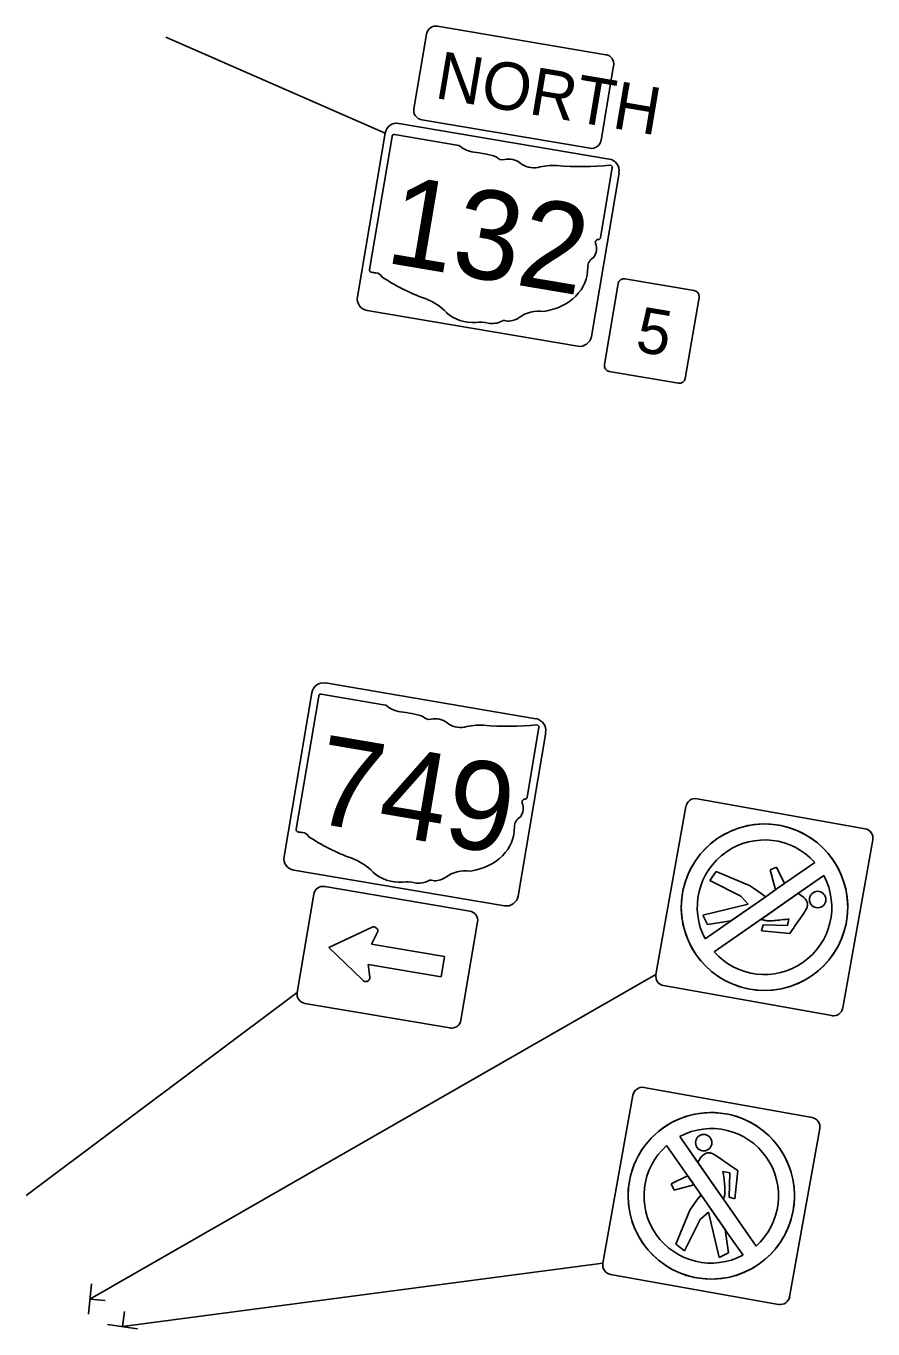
# Model space of a CAD drawing. Extents: x 1482113 to 1482447, y 365324 to 365634.
# Drawn here: x 1482304.2 to 1482393.4, y 365493.8 to 365631 of the extents above; entities that cross this region are included whole.
import ezdxf

# ---------------------------------------------------------------- set-up
doc = ezdxf.new("R2010")
doc.units = 0
doc.layers.add('RS_Raster1', color=7, linetype='Continuous')
doc.layers.add('SC_Scratch1', color=7, linetype='Continuous')

msp = doc.modelspace()

# ---------------------------------------------------------------- linework, layer by layer
at = {"layer": 'RS_Raster1'}
for p, q in [((1482342, 365619.74), (1482318.88, 365629.86)), ((1482345.03, 365622.3), (1482346.36, 365630.18)), ((1482347.52, 365631), (1482365.26, 365628)), ((1482366.08, 365626.85), (1482364.75, 365618.96)), ((1482363.6, 365618.14), (1482345.85, 365621.14)), ((1482342.73, 365619.39), (1482340.36, 365605.36)), ((1482349.77, 365618.45), (1482343, 365619.6)), ((1482364.7, 365608.73), (1482365.94, 365616.07)), ((1482364.69, 365608.74), (1482364.7, 365608.73)), ((1482369.59, 365595.95), (1482369.59, 365595.95)), ((1482335, 365560.44), (1482332.63, 365546.41)), ((1482342.04, 365559.5), (1482335.27, 365560.65)), ((1482356.97, 365549.78), (1482358.21, 365557.12)), ((1482356.96, 365549.79), (1482356.97, 365549.78)), ((1482334.48, 365539.57), (1482332.73, 365529.21)), ((1482350.91, 365537.8), (1482335.63, 365540.39)), ((1482350.91, 365537.8), (1482350.91, 365537.8)), ((1482349.98, 365526.29), (1482351.73, 365536.65)), ((1482336.07, 365533.97), (1482340.62, 365536.09)), ((1482341.17, 365535.52), (1482340.56, 365534.32)), ((1482339.62, 365530.54), (1482336.07, 365533.97)), ((1482340.56, 365534.32), (1482348.26, 365533.02)), ((1482348.26, 365533.02), (1482347.9, 365530.86)), ((1482347.9, 365530.86), (1482340.2, 365532.16)), ((1482340.2, 365532.16), (1482340.38, 365530.83)), ((1482332.73, 365529.21), (1482304.15, 365507.84)), ((1482333.54, 365528.06), (1482348.83, 365525.48))]:
    msp.add_line(p, q, dxfattribs=at)
for points in [[(1482343.44, 365620.77), (1482365.62, 365617.01)], [(1482339.08, 365602.49), (1482342, 365619.74)], [(1482366.65, 365615.57), (1482363.73, 365598.32)], [(1482365.1, 365595.35), (1482366.54, 365603.89)], [(1482367.25, 365604.39), (1482374.57, 365603.16)], [(1482375.08, 365602.44), (1482373.63, 365593.91)], [(1482362.29, 365597.29), (1482340.1, 365601.05)], [(1482372.92, 365593.4), (1482365.6, 365594.64)], [(1482335.71, 365561.82), (1482357.89, 365558.06)], [(1482331.35, 365543.54), (1482334.27, 365560.79)], [(1482358.92, 365556.62), (1482356, 365539.37)], [(1482354.56, 365538.34), (1482332.37, 365542.1)]]:
    msp.add_lwpolyline(points, dxfattribs=at)
for centre, radius, start, end in [((1482347.35, 365630.02), 1, 80.4, 170.4), ((1482365.1, 365627.02), 1, 350.4, 80.4), ((1482346.01, 365622.13), 1, 170.4, 260.4), ((1482343.23, 365619.53), 1.25, 80.4, 170.4), ((1482363.76, 365619.13), 1, 260.4, 350.4), ((1482365.41, 365615.78), 1.25, 350.4, 80.4), ((1482367.15, 365603.78), 0.618, 80.4, 170.4), ((1482340.31, 365602.28), 1.25, 170.4, 260.4), ((1482374.47, 365602.55), 0.618, 350.4, 80.4), ((1482362.5, 365598.53), 1.25, 260.4, 350.4), ((1482365.71, 365595.25), 0.618, 170.4, 260.4), ((1482373.02, 365594.01), 0.618, 260.4, 350.4), ((1482335.5, 365560.58), 1.25, 80.4, 170.4), ((1482357.68, 365556.83), 1.25, 350.4, 80.4), ((1482332.58, 365543.33), 1.25, 170.4, 260.4), ((1482335.46, 365539.4), 1, 80.4, 170.4), ((1482354.77, 365539.58), 1.25, 260.4, 350.4), ((1482350.75, 365536.81), 1, 350.4, 80.4), ((1482340.8, 365535.71), 0.417, 333.1954, 114.9888), ((1482339.96, 365530.78), 0.417, 215.3904, 7.6046), ((1482333.71, 365529.05), 1, 170.4, 260.4), ((1482349, 365526.46), 1, 260.4, 350.4)]:
    msp.add_arc(centre, radius, start, end, dxfattribs=at)
for centre, major_axis, start_param, end_param in [((1482343, 365619.38), (0.268, -0.045), 1.712693, 3.28349), ((1482351.65, 365619.81), (2.6, -0.44), 4.042523, 4.731795), ((1482350.91, 365610.16), (9.32, -1.58), 1.404758, 1.657858), ((1482354.33, 365617.54), (0.749, -0.127), 3.836095, 5.185415), ((1482355.16, 365615.73), (1.56, -0.26), 0.950623, 2.079405), ((1482357.54, 365617.61), (1.87, -0.32), 4.081561, 5.145723), ((1482360.05, 365612.3), (4.93, -0.83), 1.699011, 2.107814), ((1482360.88, 365636.25), (24.51, -4.14), 4.814394, 5.042369), ((1482365.69, 365616.15), (0.257, -0.044), 6.141152, 7.989035), ((1482361.86, 365607.71), (2.39, -0.4), 5.934695, 6.695948), ((1482364.55, 365608.21), (0.398, -0.067), 1.883978, 3.671073), ((1482364.42, 365608.75), (0.275, -0.047), 5.05454, 6.418171), ((1482365.1, 365605.51), (1.74, -0.29), 2.387724, 3.262537), ((1482340.62, 365605.29), (0.27, -0.046), 3.00124, 4.508301), ((1482340.9, 365606.71), (2.06, -0.35), 4.665946, 4.897461), ((1482340.95, 365604.43), (0.743, -0.126), 0.519207, 1.627899), ((1482357.16, 365605.89), (6.13, -1.04), 5.101752, 6.440018), ((1482352.46, 365615.45), (17.7, -2.99), 4.195997, 4.488961), ((1482344.13, 365598.24), (5.54, -0.94), 0.823519, 1.323587), ((1482351.03, 365602.65), (3.51, -0.59), 4.026481, 4.996735), ((1482358.52, 365598.24), (3.36, -0.57), 1.647645, 2.488434), ((1482352.24, 365597.46), (2.89, -0.49), 1.495662, 1.94098), ((1482353.14, 365601.21), (1.87, -0.32), 4.691044, 5.507374), ((1482354.61, 365599.57), (0.527, -0.089), 1.147584, 2.315152), ((1482354.71, 365601.54), (1.98, -0.33), 4.937069, 5.64225), ((1482335.27, 365560.43), (0.268, -0.045), 1.712693, 3.28349), ((1482343.92, 365560.86), (2.6, -0.44), 4.042523, 4.731795), ((1482343.18, 365551.21), (9.32, -1.58), 1.404758, 1.657858), ((1482346.6, 365558.59), (0.749, -0.127), 3.836095, 5.185415), ((1482347.43, 365556.78), (1.56, -0.26), 0.950623, 2.079405), ((1482349.81, 365558.66), (1.87, -0.32), 4.081561, 5.145723), ((1482352.32, 365553.35), (4.93, -0.83), 1.699011, 2.107814), ((1482353.15, 365577.3), (24.51, -4.14), 4.814394, 5.042369), ((1482357.96, 365557.2), (0.257, -0.044), 6.141152, 7.989035), ((1482354.13, 365548.76), (2.39, -0.4), 5.934695, 6.695948), ((1482356.82, 365549.26), (0.398, -0.067), 1.883978, 3.671073), ((1482356.69, 365549.8), (0.275, -0.047), 5.05454, 6.418171), ((1482357.37, 365546.56), (1.74, -0.29), 2.387724, 3.262537), ((1482332.89, 365546.34), (0.27, -0.046), 3.00124, 4.508301), ((1482333.17, 365547.76), (2.06, -0.35), 4.665946, 4.897461), ((1482333.22, 365545.48), (0.743, -0.126), 0.519207, 1.627899), ((1482349.43, 365546.94), (6.13, -1.04), 5.101752, 6.440018), ((1482344.73, 365556.5), (17.7, -2.99), 4.195997, 4.488961), ((1482336.4, 365539.29), (5.54, -0.94), 0.823519, 1.323587), ((1482343.3, 365543.7), (3.51, -0.59), 4.026481, 4.996735), ((1482350.79, 365539.29), (3.36, -0.57), 1.647645, 2.488434), ((1482344.51, 365538.51), (2.89, -0.49), 1.495662, 1.94098), ((1482345.41, 365542.26), (1.87, -0.32), 4.691044, 5.507374), ((1482346.88, 365540.62), (0.527, -0.089), 1.147584, 2.315152), ((1482346.98, 365542.59), (1.98, -0.33), 4.937069, 5.64225)]:
    msp.add_ellipse(centre, major_axis=major_axis, ratio=0.8, start_param=start_param, end_param=end_param, dxfattribs=at)
at = {"layer": 'SC_Scratch1'}
for p, q in [((1482376.88, 365541.95), (1482376.2, 365541.03)), ((1482376.88, 365541.95), (1482376.2, 365541.03)), ((1482380.45, 365540.46), (1482376.88, 365541.95)), ((1482380.45, 365540.46), (1482376.88, 365541.95)), ((1482383.23, 365542.43), (1482382.58, 365542.13)), ((1482383.23, 365542.43), (1482382.58, 365542.13)), ((1482382.58, 365542.13), (1482383.14, 365540.04)), ((1482382.58, 365542.13), (1482383.14, 365540.04)), ((1482384.1, 365540.71), (1482383.23, 365542.43)), ((1482384.09, 365540.71), (1482383.23, 365542.43)), ((1482376.2, 365541.03), (1482379.49, 365539.37)), ((1482376.2, 365541.03), (1482379.49, 365539.37)), ((1482388.24, 365541.54), (1482376.68, 365533.49)), ((1482381.62, 365539.65), (1482380.45, 365540.46)), ((1482381.62, 365539.65), (1482380.45, 365540.46)), ((1482378.42, 365536.75), (1482382, 365539.24)), ((1482379.49, 365539.37), (1482380.25, 365538.51)), ((1482379.49, 365539.37), (1482380.25, 365538.51)), ((1482382.07, 365539.29), (1482381.62, 365539.65)), ((1482382.07, 365539.29), (1482381.62, 365539.65)), ((1482385.4, 365539.56), (1482381.66, 365536.95)), ((1482382, 365539.24), (1482382.07, 365539.29)), ((1482383.14, 365540.04), (1482383.33, 365540.17)), ((1482385.52, 365539.64), (1482385.4, 365539.56)), ((1482380.25, 365538.51), (1482375.47, 365537.37)), ((1482380.25, 365538.51), (1482375.47, 365537.37)), ((1482375.47, 365537.37), (1482375.97, 365536.38)), ((1482375.47, 365537.37), (1482375.97, 365536.38)), ((1482375.97, 365536.38), (1482378.42, 365536.75)), ((1482375.97, 365536.38), (1482378.42, 365536.75)), ((1482381.84, 365536.34), (1482381.67, 365535.73)), ((1482381.84, 365536.34), (1482381.67, 365535.73)), ((1482384.4, 365536.26), (1482381.84, 365536.34)), ((1482384.4, 365536.26), (1482381.84, 365536.34)), ((1482384.55, 365536.97), (1482384.4, 365536.26)), ((1482384.55, 365536.97), (1482384.4, 365536.26)), ((1482381.67, 365535.73), (1482384.66, 365535.42)), ((1482381.67, 365535.73), (1482384.66, 365535.42)), ((1482384.66, 365535.42), (1482384.66, 365535.44)), ((1482384.66, 365535.42), (1482384.66, 365535.44)), ((1482310.88, 365496.92), (1482370.54, 365531.1)), ((1482373.04, 365514.06), (1482381.09, 365502.5)), ((1482374.94, 365511.34), (1482375.02, 365511.22)), ((1482375.02, 365511.22), (1482377.62, 365507.48)), ((1482377.6, 365510.38), (1482378.32, 365510.22)), ((1482377.6, 365510.38), (1482378.32, 365510.22)), ((1482378.85, 365507.49), (1482379.16, 365510.48)), ((1482378.85, 365507.49), (1482379.16, 365510.48)), ((1482379.16, 365510.48), (1482379.14, 365510.48)), ((1482379.16, 365510.48), (1482379.14, 365510.48)), ((1482373.87, 365509.92), (1482372.15, 365509.05)), ((1482373.87, 365509.92), (1482372.15, 365509.05)), ((1482372.15, 365509.05), (1482372.45, 365508.41)), ((1482372.15, 365509.05), (1482372.45, 365508.41)), ((1482372.45, 365508.41), (1482374.54, 365508.96)), ((1482372.45, 365508.41), (1482374.54, 365508.96)), ((1482374.54, 365508.96), (1482374.41, 365509.15)), ((1482378.32, 365510.22), (1482378.24, 365507.66)), ((1482378.32, 365510.22), (1482378.24, 365507.66)), ((1482375.29, 365507.89), (1482374.93, 365507.44)), ((1482375.29, 365507.89), (1482374.93, 365507.44)), ((1482375.33, 365507.82), (1482375.29, 365507.89)), ((1482377.83, 365504.25), (1482375.33, 365507.82)), ((1482378.24, 365507.66), (1482378.85, 365507.49)), ((1482378.24, 365507.66), (1482378.85, 365507.49)), ((1482374.12, 365506.28), (1482372.63, 365502.71)), ((1482374.12, 365506.28), (1482372.63, 365502.71)), ((1482374.93, 365507.44), (1482374.12, 365506.28)), ((1482374.93, 365507.44), (1482374.12, 365506.28)), ((1482373.55, 365502.02), (1482375.21, 365505.31)), ((1482373.55, 365502.02), (1482375.21, 365505.31)), ((1482375.21, 365505.31), (1482376.07, 365506.08)), ((1482375.21, 365505.31), (1482376.07, 365506.08)), ((1482376.07, 365506.08), (1482377.21, 365501.29)), ((1482376.07, 365506.08), (1482377.21, 365501.29)), ((1482378.2, 365501.79), (1482377.83, 365504.25)), ((1482378.2, 365501.79), (1482377.83, 365504.25)), ((1482372.63, 365502.71), (1482373.55, 365502.02)), ((1482372.63, 365502.71), (1482373.55, 365502.02)), ((1482314.31, 365494.02), (1482364.95, 365500.69)), ((1482377.21, 365501.29), (1482378.2, 365501.79)), ((1482377.21, 365501.29), (1482378.2, 365501.79)), ((1482310.73, 365495.33), (1482311.04, 365498.52)), ((1482310.88, 365496.92), (1482312.48, 365496.77)), ((1482314.31, 365494.02), (1482314.54, 365495.6)), ((1482315.89, 365493.78), (1482312.72, 365494.25))]:
    msp.add_line(p, q, dxfattribs=at)
for points in [[(1482373.7, 365548.82), (1482370.54, 365531.1)], [(1482392.58, 365546.47), (1482374.87, 365549.63)], [(1482390.23, 365527.59), (1482393.39, 365545.31)], [(1482387.27, 365542.92), (1482384.13, 365540.73), (1482383.33, 365540.16), (1482383.33, 365540.17)], [(1482383.33, 365540.17), (1482384.09, 365540.71), (1482384.09, 365540.71)], [(1482385.4, 365539.56), (1482388.24, 365541.54)], [(1482383.33, 365540.17), (1482382, 365539.24), (1482377.7, 365536.24), (1482375.72, 365534.86)], [(1482376.68, 365533.49), (1482381.27, 365536.68), (1482381.27, 365536.68), (1482381.27, 365536.68), (1482385.4, 365539.56), (1482385.39, 365539.56)], [(1482385.4, 365539.56), (1482385.4, 365539.56)], [(1482371.35, 365529.94), (1482389.07, 365526.78)], [(1482386.99, 365516.05), (1482369.27, 365519.22)], [(1482368.11, 365518.41), (1482364.95, 365500.69)], [(1482384.63, 365497.17), (1482387.8, 365514.89)], [(1482371.66, 365513.1), (1482373.85, 365509.95), (1482374.41, 365509.16), (1482374.41, 365509.15)], [(1482375.02, 365511.22), (1482373.04, 365514.06)], [(1482381.09, 365502.51), (1482377.9, 365507.09), (1482377.9, 365507.09), (1482377.9, 365507.09), (1482375.02, 365511.22), (1482375.02, 365511.22)], [(1482375.02, 365511.22), (1482375.02, 365511.22)], [(1482374.41, 365509.15), (1482373.87, 365509.92), (1482373.87, 365509.92)], [(1482374.41, 365509.15), (1482375.33, 365507.82), (1482378.33, 365503.53), (1482379.72, 365501.55)], [(1482365.76, 365499.53), (1482383.47, 365496.36)]]:
    msp.add_lwpolyline(points, dxfattribs=at)
for centre, radius in [((1482381.98, 365538.2), 8.77), ((1482387.58, 365539.01), 0.864), ((1482376.37, 365507.8), 8.77), ((1482375.57, 365513.4), 0.864)]:
    msp.add_circle(centre, radius, dxfattribs=at)
for centre, radius, start, end in [((1482374.69, 365548.65), 1, 79.8676, 169.8676), ((1482381.98, 365538.2), 8.77, 79.8676, 259.8676), ((1482381.98, 365538.2), 8.77, 259.8676, 79.8676), ((1482392.41, 365545.48), 1, 349.8676, 79.8676), ((1482381.98, 365538.2), 7.09, 41.7155, 208.1155), ((1482381.98, 365538.2), 7.09, 41.7155, 208.1155), ((1482381.98, 365538.2), 7.09, 221.6867, 28.0389), ((1482381.98, 365538.2), 7.09, 221.6867, 28.0389), ((1482384.25, 365538.53), 1.54, 41.9428, 41.9959), ((1482371.52, 365530.93), 1, 169.8676, 259.8676), ((1482389.24, 365527.76), 1, 259.8676, 349.8676), ((1482369.1, 365518.23), 1, 79.8676, 169.8676), ((1482376.37, 365507.8), 8.77, 349.8676, 169.8676), ((1482386.82, 365515.06), 1, 349.8676, 79.8676), ((1482376.37, 365507.8), 7.09, 311.6867, 118.0389), ((1482376.37, 365507.8), 7.09, 311.6867, 118.0389), ((1482376.37, 365507.8), 7.09, 131.7155, 298.1155), ((1482376.37, 365507.8), 7.09, 131.7155, 298.1155), ((1482376.05, 365510.08), 1.54, 131.9428, 131.9959), ((1482376.37, 365507.8), 8.77, 169.8676, 349.8676), ((1482365.93, 365500.51), 1, 169.8676, 259.8676), ((1482383.65, 365497.35), 1, 259.8676, 349.8676)]:
    msp.add_arc(centre, radius, start, end, dxfattribs=at)
for points in [[(1482384.66, 365535.44), (1482385.2, 365536.24), (1482386.06, 365537.5), (1482386.38, 365537.96), (1482386.45, 365538.12), (1482386.48, 365538.28), (1482386.55, 365538.68), (1482386.17, 365539.26), (1482385.76, 365539.49), (1482385.52, 365539.64)], [(1482384.66, 365535.44), (1482385.2, 365536.24), (1482386.06, 365537.5), (1482386.38, 365537.96), (1482386.45, 365538.12), (1482386.48, 365538.28), (1482386.55, 365538.68), (1482386.17, 365539.26), (1482385.76, 365539.49), (1482385.52, 365539.64)], [(1482381.66, 365536.95), (1482381.72, 365536.91), (1482381.91, 365536.81), (1482382.37, 365536.76), (1482382.79, 365536.77), (1482383.54, 365536.84), (1482384.06, 365536.9), (1482384.55, 365536.97)], [(1482381.66, 365536.95), (1482381.72, 365536.91), (1482381.91, 365536.81), (1482382.37, 365536.76), (1482382.79, 365536.77), (1482383.54, 365536.84), (1482384.06, 365536.9), (1482384.55, 365536.97)], [(1482379.14, 365510.48), (1482378.34, 365511.02), (1482377.08, 365511.89), (1482376.62, 365512.21), (1482376.46, 365512.27), (1482376.3, 365512.3), (1482375.9, 365512.37), (1482375.32, 365511.99), (1482375.09, 365511.59), (1482374.94, 365511.34)], [(1482379.14, 365510.48), (1482378.34, 365511.02), (1482377.08, 365511.89), (1482376.62, 365512.21), (1482376.46, 365512.27), (1482376.3, 365512.3), (1482375.9, 365512.37), (1482375.32, 365511.99), (1482375.09, 365511.59), (1482374.94, 365511.34)], [(1482377.62, 365507.48), (1482377.67, 365507.54), (1482377.77, 365507.74), (1482377.82, 365508.19), (1482377.81, 365508.62), (1482377.74, 365509.36), (1482377.68, 365509.88), (1482377.6, 365510.38)], [(1482377.62, 365507.48), (1482377.67, 365507.54), (1482377.77, 365507.74), (1482377.82, 365508.19), (1482377.81, 365508.62), (1482377.74, 365509.36), (1482377.68, 365509.88), (1482377.6, 365510.38)]]:
    msp.add_open_spline(points, degree=3, dxfattribs=at)

# ---------------------------------------------------------------- texts
at = {"layer": 'RS_Raster1'}
for s, height, p in [('NORTH', 5, (1482347.12, 365623.46)), ('132', 9.375, (1482341.84, 365606.13)), (' 5', 4.776, (1482366.49, 365597.08)), ('749', 9.375, (1482334.08, 365547.18))]:
    msp.add_text(s, height=height, rotation=350.4, dxfattribs=at).set_placement(p)

doc.saveas('drawing.dxf')
